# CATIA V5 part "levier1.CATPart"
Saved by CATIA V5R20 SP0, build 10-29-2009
Part number: levier1
Bounding box of the stored display mesh (mm): x -20 to 20, y -110 to 220, z 980 to 1370
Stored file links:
  D:\Dropbox\Pack 1 sylvain\mmoreau\mmoreau\mmoreau\fin\levier1.CATPart
  U:\think motion\fin\think motion2.CATProduct
  D:\Dropbox\Pack 1 sylvain\mmoreau\mmoreau\mmoreau\fin\levier2.CATPart
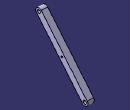
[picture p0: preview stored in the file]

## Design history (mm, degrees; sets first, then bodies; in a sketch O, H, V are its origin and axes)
External parameters (linked from other documents)
  `External.largeur levier` = 40 mm
Set1
  Plane1: linked copy from another document
  Line1: linked copy from another document
  Point1: linked copy from another document
  Point2: linked copy from another document
  Line2: linked copy from another document
Body1 (main body)
  Sketch1 on Plane1, origin (0, 0, 0), H (0, 1, 0), V (0, 0, 1)
    line L1 (-74.5996, 1362.7604) -> (215.4004, 1012.7604)
    reference projected line E1 (-34.5963, 1283.1335) -> (543.982, 584.8493) from Line1
    reference projected line E2 (-34.5963, 1283.1335) -> (543.982, 584.8493) from Line1
    reference projected line E3 (-90, 1350) -> (200, 1000) from edge of Line1
    line L2 (-105.4004, 1337.2396) -> (184.5996, 987.2396)
    arc A1 centre (-90, 1350) radius 20 from (-74.5996, 1362.7604) to (-105.4004, 1337.2396) ccw
    circle A2 centre (-90, 1350) radius 10
    arc A3 centre (200, 1000) radius 20 from (184.5996, 987.2396) to (215.4004, 1012.7604) ccw
    point P5 (200, 1000)
    reference projected point E4 (200, 1000) from Point1
    circle A4 centre (200, 1000) radius 10
    point P8 (206.3802, 992.2998)
    distance E2 L1 = 20
    radius A2 = 10
    radius A4 = 10
    parallelism: E1 L1
    symmetry: L1 L2 E3
    tangency: A1 L1, A3 L1
    coincidence: P5 E4, A4 P8, P8 E3
  Pad1: profile Sketch1, direction (1, 0, 0), length 20 {= `External.largeur levier` /2}, mirrored extent
  Sketch2 on start face of Pad1, origin (-20, 504.8723, 1178.9237), H (0, 1, 0), V (0, 0, -1)
    point P1 (-449.8723, 3.9237)
    reference projected point E1 (-449.8723, 3.9237) from Point2
    coincidence: E1 P1
  Hole1: placed by Sketch2, at (-20, 55, 1175) direction (1, 0, 0), diameter 10, through (limit type 3)
  Sketch3 on face of Pad1 from Sketch1.L2, origin (0, 594.4737, 492.5639), H (1, 0, 0), V (0, -0.638, 0.77)
    construction line L1 (0, 889.6844) -> (0, 839.6844)
    point P1 (0, 889.6844)
    point P2 (0, 839.6844)
    line L2 (15, 889.6844) -> (15, 839.6844)
    line L3 (-15, 839.6844) -> (-15, 889.6844)
    arc A1 centre (0, 839.6844) radius 15 from (15, 839.6844) to (-15, 839.6844) cw
    arc A2 centre (0, 889.6844) radius 15 from (-15, 889.6844) to (15, 889.6844) cw
    reference projected line E1 (0, 1096.9507) -> (0, 642.418) from Line1
    reference projected point E2 (0, 869.6844) from Point2
    reference projected point E3 (0, 869.6844) from Point2
    reference projected point E4 (0, 869.6844) from Point2
    reference projected point E5 (0, 869.6844) from Point2
    distance L1 L2 = 15
    distance E2 E3 = 0 (reference)
    distance E4 P2 = 30
    distance E5 P1 = 20
    vertical: L1 V
    tangency: A1 L2, A2 L2, A1 L3, A2 L3
    symmetry: L2 L3 E1
  Pocket1: profile Sketch3, direction (0, 0.77, 0.638), length 30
